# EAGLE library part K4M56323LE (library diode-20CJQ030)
SAMSUNG's K4M56323LE - R(B)G/F Mobile-SDRAM 2M x 32Bit x 4 Banks Mobile SDRAM in 90FBGA Organization : 8Mx32 Vdd/Vddq : 2.5V / 2.5V Icc1/Icc6 : 140mA/1000uA Speed : 125MHz, CL2; 105MHz, CL2; 105MHz, CL3 Features: 2.5V power supply. LVCMOS compatible with multiplexed address. Four banks operation. MRS cycle with address key programs. -. CAS latency (1, 2 & 3). -. Burst length (1, 2, 4, 8 & Full page). -. Burst type (Sequential & Interleave). EMRS cycle with address key programs. All inputs are sampled at the positive going edge of the system clock. Burst read single-bit write operation. Special Function Support. -. PASR (Partial Array Self Refresh). -. Internal TCSR (Temperature Compensated Self Refresh) DQM for masking. Auto refresh. 64ms refresh period (4K cycle). Commercial Temperature Operation (-25°C ~ 70°C). Extended Temperature Operation (-25°C ~ 85°C). 2Chips DDP 90Balls FBGA with 0.8mm ball pitch ( -MXXX : Leaded, -EXXX : Lead Free). Description: The K4M56323LE is 268,435,456 bits synchronous high data rate Dynamic RAM organized as 4 x 2,097,152 words by 32 bits, fabricated with SAMSUNG's high performance CMOS technology. Synchronous design allows precise cycle control with the use of system clock and I/O transactions are possible on every clock cycle. Range of operating frequencies, programmable burst lengths and programmable latencies allow the same device to be useful for a variety of high bandwidth and high performance memory system applications. Please send any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
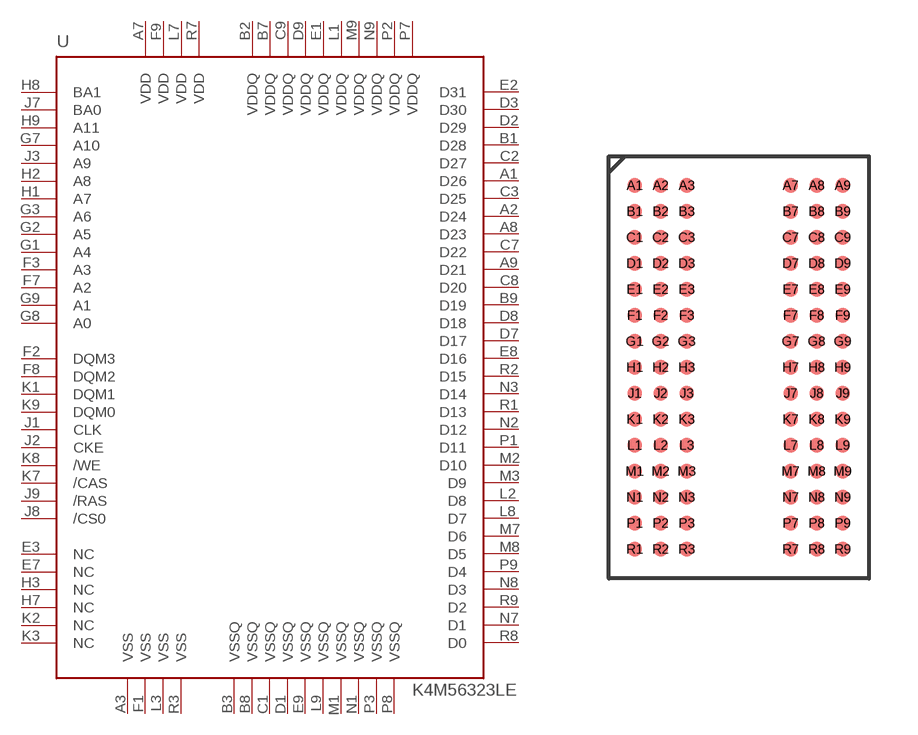
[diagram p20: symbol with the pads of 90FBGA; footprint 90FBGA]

Designator prefix U

## K4M56323LE  [90FBGA]
A1  D26
A2  D24
A3  VSS  pwr
A7  VDD  pwr
A8  D23
A9  D21
B1  D28
B2  VDDQ  pwr
B3  VSSQ  pwr
B7  VDDQ  pwr
B8  VSSQ  pwr
B9  D19
C1  VSSQ  pwr
C2  D27
C3  D25
C7  D22
C8  D20
C9  VDDQ  pwr
D1  VSSQ  pwr
D2  D29
D3  D30
D7  D17
D8  D18
D9  VDDQ  pwr
E1  VDDQ  pwr
E2  D31
E3  NC  nc
E7  NC  nc
E8  D16
E9  VSSQ  pwr
F1  VSS  pwr
F2  DQM3
F3  A3
F7  A2
F8  DQM2
F9  VDD  pwr
G1  A4
G2  A5
G3  A6
G7  A10
G8  A0
G9  A1
H1  A7
H2  A8
H3  NC  nc
H7  NC  nc
H8  BA1
H9  A11
J1  CLK
J2  CKE
J3  A9
J7  BA0
J8  /CS0
J9  /RAS
K1  DQM1
K2  NC  nc
K3  NC  nc
K7  /CAS
K8  /WE
K9  DQM0
L1  VDDQ  pwr
L2  D8
L3  VSS  pwr
L7  VDD  pwr
L8  D7
L9  VSSQ  pwr
M1  VSSQ  pwr
M2  D10
M3  D9
M7  D6
M8  D5
M9  VDDQ  pwr
N1  VSSQ  pwr
N2  D12
N3  D14
N7  D1
N8  D3
N9  VDDQ  pwr
P1  D11
P2  VDDQ  pwr
P3  VSSQ  pwr
P7  VDDQ  pwr
P8  VSSQ  pwr
P9  D4
R1  D13
R2  D15
R3  VSS  pwr
R7  VDD  pwr
R8  D0
R9  D2

## Footprint 90FBGA (pad centres in mm)
90 PIN FBGA Pitch: 0.8mm balldiameter 0.5mm Please send any comments to: messi@users.sourceforge.net
smd 0.45 x 0.45: A1 -3.2,5.6; A2 -2.4,5.6; A3 -1.6,5.6; A7 1.6,5.6; A8 2.4,5.6; A9 3.2,5.6; B1 -3.2,4.8; B2 -2.4,4.8; B3 -1.6,4.8; B7 1.6,4.8; B8 2.4,4.8; B9 3.2,4.8; C1 -3.2,4; C2 -2.4,4; C3 -1.6,4; C7 1.6,4; C8 2.4,4; C9 3.2,4; D1 -3.2,3.2; D2 -2.4,3.2; D3 -1.6,3.2; D7 1.6,3.2; D8 2.4,3.2; D9 3.2,3.2; E1 -3.2,2.4; E2 -2.4,2.4; E3 -1.6,2.4; E7 1.6,2.4; E8 2.4,2.4; E9 3.2,2.4; F1 -3.2,1.6; F2 -2.4,1.6; F3 -1.6,1.6; F7 1.6,1.6; F8 2.4,1.6; F9 3.2,1.6; G1 -3.2,0.8; G2 -2.4,0.8; G3 -1.6,0.8; G7 1.6,0.8; G8 2.4,0.8; G9 3.2,0.8; H1 -3.2,0; H2 -2.4,0; H3 -1.6,0; H7 1.6,0; H8 2.4,0; H9 3.2,0; J1 -3.2,-0.8; J2 -2.4,-0.8; J3 -1.6,-0.8; J7 1.6,-0.8; J8 2.4,-0.8; J9 3.2,-0.8; K1 -3.2,-1.6; K2 -2.4,-1.6; K3 -1.6,-1.6; K7 1.6,-1.6; K8 2.4,-1.6; K9 3.2,-1.6; L1 -3.2,-2.4; L2 -2.4,-2.4; L3 -1.6,-2.4; L7 1.6,-2.4; L8 2.4,-2.4; L9 3.2,-2.4; M1 -3.2,-3.2; M2 -2.4,-3.2; M3 -1.6,-3.2; M7 1.6,-3.2; M8 2.4,-3.2; M9 3.2,-3.2; N1 -3.2,-4; N2 -2.4,-4; N3 -1.6,-4; N7 1.6,-4; N8 2.4,-4; N9 3.2,-4; P1 -3.2,-4.8; P2 -2.4,-4.8; P3 -1.6,-4.8; P7 1.6,-4.8; P8 2.4,-4.8; P9 3.2,-4.8; R1 -3.2,-5.6; R2 -2.4,-5.6; R3 -1.6,-5.6; R7 1.6,-5.6; R8 2.4,-5.6; R9 3.2,-5.6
